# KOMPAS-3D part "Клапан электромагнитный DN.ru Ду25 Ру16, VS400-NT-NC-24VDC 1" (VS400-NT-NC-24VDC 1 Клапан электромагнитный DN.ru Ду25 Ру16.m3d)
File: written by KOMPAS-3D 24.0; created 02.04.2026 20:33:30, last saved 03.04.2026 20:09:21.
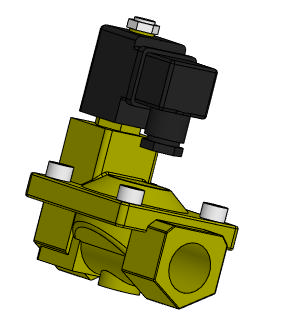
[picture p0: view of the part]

Document properties: Автор: artio; Полное имя файла: C:\Users\artio\OneDrive\Рабочий стол\Клапан электромагнитный DN.ru\VS400-NT-NC\VS400-NT-NC-24VDC 1 Клапан электромагнитный DN.ru Ду25 Ру16.m3d

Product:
- Body: Тело 1  | qty 1
    Масса: 1.76797
- Part/product: Клапан электромагнитный DN.ru Ду25 Ру16  | designation VS400-NT-NC-24VDC 1
    Масса: 1.524
    Раздел спецификации: Прочие изделия
    Примечание: D130-04728
    additional columns: ef56311e-7521-43dc-8291-0e6108b3d81d; VS400-ET-NC-220VAC 1; artio; c; Шероховатость не задана; Да

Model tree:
1. Операция без истории:1

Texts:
  VS400-NT-NC-24VDC 1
